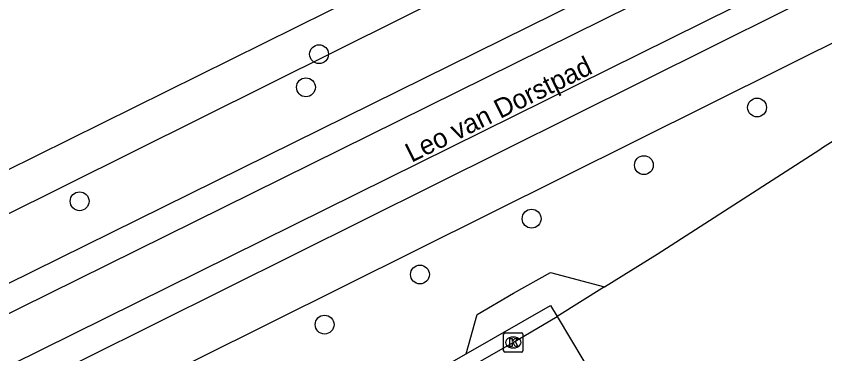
# Model space of a CAD drawing. Extents: x 157321 to 158827, y 386650 to 388532.
# Drawn here: x 158355.78 to 158397.76, y 386946.11 to 386963.61 of the extents above; entities that cross this region are included whole.
import ezdxf

# ---------------------------------------------------------------- set-up
doc = ezdxf.new("R2010")
doc.units = 0
for name, color, linetype in [('IMGEO_Boom', 7, 'Continuous'), ('IMGEO_Fietspad_gesloten', 7, 'Continuous'), ('IMGEO_Kolk', 7, 'Continuous'), ('IMGEO_Openbare_ruimte_label', 7, 'Continuous'), ('IMGEO_Rijbaan_lokaal_gesloten', 7, 'Continuous'), ('IMGEO_Rijbaan_lokaal_open', 7, 'Continuous'), ('IMGEO_Voetpad_open', 7, 'Continuous'), ('IMGEO_Waterloop', 7, 'Continuous')]:
    doc.layers.add(name, color=color, linetype=linetype)

msp = doc.modelspace()

# ---------------------------------------------------------------- linework, layer by layer
at = {"layer": 'IMGEO_Boom'}
for centre in [(158371.507, 386961.64), (158370.825, 386959.922), (158394.241, 386958.876), (158388.369, 386955.889), (158359.078, 386954.017), (158382.54, 386953.114), (158376.744, 386950.22), (158371.794, 386947.622)]:
    msp.add_circle(centre, 0.489, dxfattribs=at)
at = {"layer": 'IMGEO_Fietspad_gesloten'}
for points in [[(158323.412, 386932.416), (158324.19, 386932.8), (158457.336, 386998.52), (158460.314, 387000), (158484.901, 387012.221)], [(158326.206, 386931.101), (158327.714, 386931.826), (158458.366, 386996.365), (158465.686, 387000), (158486.098, 387010.137)]]:
    msp.add_lwpolyline(points, dxfattribs=at)
at = {"layer": 'IMGEO_Kolk'}
for p, q in [((158381.163, 386947.196), (158382.015, 386947.196)), ((158381.088, 386946.27), (158381.088, 386947.122)), ((158381.576, 386946.976), (158381.601, 386946.976)), ((158382.089, 386947.122), (158382.089, 386946.27)), ((158381.599, 386946.416), (158381.574, 386946.416)), ((158382.015, 386946.196), (158381.163, 386946.196))]:
    msp.add_line(p, q, dxfattribs=at)
for points in [[(158381.163, 386947.196), (158382.015, 386947.196)], [(158381.088, 386946.27), (158381.088, 386947.122)], [(158381.409, 386946.896), (158381.532, 386946.896), (158381.532, 386946.745), (158381.662, 386946.896), (158381.826, 386946.896), (158381.68, 386946.745), (158381.833, 386946.496), (158381.681, 386946.496), (158381.596, 386946.66), (158381.532, 386946.593), (158381.532, 386946.496), (158381.409, 386946.496), (158381.409, 386946.896)], [(158382.089, 386947.122), (158382.089, 386946.27)], [(158382.015, 386946.196), (158381.163, 386946.196)]]:
    msp.add_lwpolyline(points, dxfattribs=at)
for centre, start, end in [((158381.165, 386947.12), 91.552, 178.448), ((158381.165, 386947.12), 91.552, 178.448), ((158382.013, 386947.12), 1.552, 88.448), ((158382.013, 386947.12), 1.552, 88.448), ((158381.165, 386946.272), 181.552, 268.448), ((158381.165, 386946.272), 181.552, 268.448), ((158382.013, 386946.272), 271.552, 358.448), ((158382.013, 386946.272), 271.552, 358.448)]:
    msp.add_arc(centre, 0.0765, start, end, dxfattribs=at)
for centre, major_axis, ratio, start_param, end_param in [((158381.575, 386946.696), (-0.387, 0.002), 0.722429, 4.712389, 7.853982), ((158381.6, 386946.696), (-0.39, 0.002), 0.717154, 1.570796, 4.712389)]:
    msp.add_ellipse(centre, major_axis=major_axis, ratio=ratio, start_param=start_param, end_param=end_param, dxfattribs=at)
at = {"layer": 'IMGEO_Rijbaan_lokaal_gesloten'}
for points in [[(158379.145, 386946.114), (158379.71, 386948.144), (158381.6, 386949.261), (158383.52, 386950.324), (158386.332, 386949.577)], [(158386.332, 386949.577), (158383.872, 386948.041)], [(158379.145, 386946.114), (158383.528, 386948.618), (158383.872, 386948.041)], [(158375.59, 386943.272), (158381.545, 386946.671), (158383.489, 386947.813), (158383.872, 386948.041)], [(158383.872, 386948.041), (158385.885, 386944.662)]]:
    msp.add_lwpolyline(points, dxfattribs=at)
at = {"layer": 'IMGEO_Rijbaan_lokaal_open'}
msp.add_lwpolyline([(158386.332, 386949.577), (158389.058, 386951.279), (158397.495, 386956.697), (158397.633, 386956.804), (158407.389, 386962.865), (158411.175, 386956.558)], dxfattribs=at)
at = {"layer": 'IMGEO_Voetpad_open'}
for points in [[(158484.31, 387013.395), (158457.303, 387000), (158456.763, 386999.732), (158324.179, 386934.371)], [(158375.59, 386943.272), (158375.236, 386943.88), (158379.145, 386946.114)]]:
    msp.add_lwpolyline(points, dxfattribs=at)
at = {"layer": 'IMGEO_Waterloop'}
for points in [[(158344.392, 386947.927), (158449.198, 387000), (158471.845, 387010.79), (158478.89, 387013.927), (158477.892, 387016.018), (158444.567, 387000), (158408.899, 386982.116), (158343.439, 386949.753)], [(158432.84, 386979.734), (158431.701, 386981.819), (158344.904, 386938.678), (158346.119, 386936.364)], [(158346.119, 386936.364), (158410.819, 386968.542), (158432.84, 386979.734)]]:
    msp.add_lwpolyline(points, dxfattribs=at)

# ---------------------------------------------------------------- texts
at = {"layer": 'IMGEO_Openbare_ruimte_label'}
msp.add_text('Leo van Dorstpad', height=1, rotation=26.2319, dxfattribs=at).set_placement((158376.304, 386956.007))

doc.saveas('drawing.dxf')
